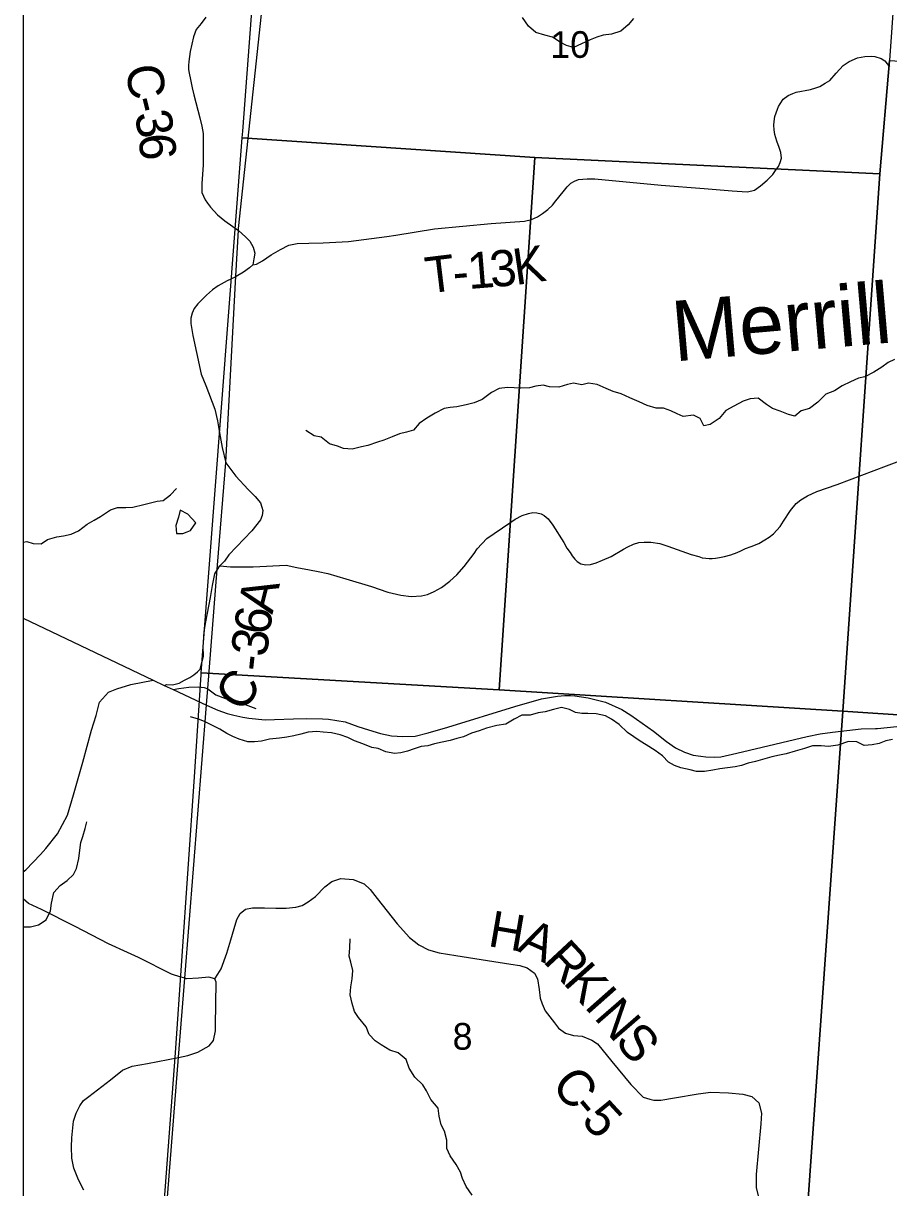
# Model space of a CAD drawing. Extents: x -8.2 to 34, y 0 to 22.
# Drawn here: x 2.1 to 3.458, y 17.043 to 18.871 of the extents above; entities that cross this region are included whole.
import ezdxf

# ---------------------------------------------------------------- set-up
doc = ezdxf.new("R2010")
doc.units = 0
for name, color, linetype in [('GM_X_Corporation', 7, 'Continuous'), ('GM_X_County_Road', 7, 'Continuous'), ('GM_X_County_Road_Text', 7, 'Continuous'), ('GM_X_Minor_Lake', 7, 'Continuous'), ('GM_X_Minor_River', 7, 'Continuous'), ('GM_X_Minor_River_Text', 7, 'Continuous'), ('GM_X_Section_Text', 7, 'Continuous'), ('GM_X_Township_Road', 7, 'Continuous'), ('GM_X_Township_Road_Text', 7, 'Continuous'), ('GM_X_Township_Text', 7, 'Continuous'), ('GM_X_US_Route', 7, 'Continuous'), ('SH_Data', 7, 'Continuous')]:
    doc.layers.add(name, color=color, linetype=linetype)

msp = doc.modelspace()

# ---------------------------------------------------------------- linework, layer by layer
at = {"layer": 'GM_X_Corporation'}
msp.add_lwpolyline([(6.4774, 18.0203), (6.488, 18.1752), (6.5242, 18.7061), (6.5297, 18.7882), (6.5448, 18.981), (6.5455, 18.9878), (6.5461, 19.0017), (6.5463, 19.009), (6.5469, 19.0218), (6.548, 19.0467), (6.5487, 19.0617), (6.5495, 19.0821), (6.5503, 19.0966), (6.5514, 19.1092), (6.5523, 19.118), (6.5529, 19.1264), (6.5537, 19.1382), (6.5541, 19.1447), (6.5536, 19.1514), (6.5814, 19.5334), (6.6608, 20.6695), (6.6768, 20.9), (2.1, 20.9), (2.1, 14.1)], dxfattribs=at)
for points in [[(2.4767, 19.0935), (3.474, 19.0276), (3.459, 18.8121), (3.4438, 18.6343), (2.9025, 18.6602), (2.4436, 18.691), (2.4444, 18.7015), (2.4582, 18.8825)], [(4.465, 18.749), (4.3947, 17.7241), (3.3856, 17.7912), (3.4438, 18.6343), (3.459, 18.8121)], [(2.9025, 18.6602), (2.8467, 17.8246), (2.3793, 17.8512), (2.4436, 18.691)], [(3.4438, 18.6343), (3.3856, 17.7912), (2.8467, 17.8246), (2.9025, 18.6602)], [(2.3791, 17.8483), (2.3793, 17.8512), (2.8467, 17.8246), (3.3856, 17.7912), (3.312, 16.7534), (2.3064, 16.8225), (2.3386, 17.2548), (2.3688, 17.6879)], [(3.3856, 17.7912), (4.3947, 17.7241), (4.3249, 16.693), (3.312, 16.7534)]]:
    msp.add_lwpolyline(points, close=True, dxfattribs=at)
at = {"layer": 'GM_X_County_Road'}
for points in [[(2.3864, 18.8801), (2.3791, 18.8703), (2.3714, 18.861), (2.3673, 18.8497), (2.3644, 18.8381), (2.3616, 18.8265), (2.3606, 18.8187), (2.3595, 18.8107), (2.359, 18.8046), (2.3593, 18.7981), (2.3603, 18.7927), (2.3624, 18.7824), (2.3652, 18.7692), (2.3678, 18.7587), (2.3771, 18.7226), (2.3799, 18.7094), (2.382, 18.6978), (2.3822, 18.6483), (2.3799, 18.6191), (2.3802, 18.605), (2.3853, 18.5939), (2.3892, 18.5885)], [(2.3892, 18.5885), (2.3936, 18.5823), (2.4049, 18.5699), (2.416, 18.5609), (2.4374, 18.5456), (2.4488, 18.5358), (2.4552, 18.5286), (2.4604, 18.5196), (2.4632, 18.5098), (2.4617, 18.5008), (2.4602, 18.4916), (2.4549, 18.4869), (2.4456, 18.4803), (2.4338, 18.4731), (2.4322, 18.4721), (2.4199, 18.4663), (2.406, 18.4585), (2.3971, 18.4522), (2.3874, 18.4441), (2.3804, 18.4374), (2.3738, 18.4302), (2.3683, 18.423), (2.3651, 18.416), (2.363, 18.4077), (2.3626, 18.3998), (2.3658, 18.3808), (2.3715, 18.3542), (2.3793, 18.3201), (2.3862, 18.3025), (2.4005, 18.2649), (2.4045, 18.247), (2.4079, 18.2277), (2.4119, 18.2052), (2.4179, 18.1808), (2.4335, 18.1598), (2.4528, 18.139), (2.4637, 18.1282), (2.472, 18.1181), (2.4742, 18.1111), (2.4759, 18.1058), (2.4748, 18.0984), (2.4723, 18.0914), (2.4587, 18.0744), (2.4227, 18.0363), (2.4159, 18.0264), (2.4084, 18.0194), (2.425, 18.0175), (2.434, 18.0175), (2.4608, 18.0179), (2.5126, 18.0204), (2.5292, 18.0167), (2.5491, 18.013), (2.5626, 18.0105), (2.578, 18.0072), (2.6058, 17.9989), (2.6461, 17.9866), (2.6721, 17.978), (2.6922, 17.9731), (2.7086, 17.971), (2.7247, 17.972), (2.7342, 17.9741), (2.7446, 17.9788), (2.7563, 17.9854), (2.769, 17.9952), (2.78, 18.0052), (2.7915, 18.0181), (2.8072, 18.0384), (2.812, 18.0459), (2.8273, 18.0619), (2.8633, 18.0867), (2.8719, 18.0924), (2.8826, 18.0984), (2.8924, 18.1014), (2.8996, 18.1029), (2.9059, 18.1025), (2.9123, 18.1008), (2.917, 18.0982), (2.9235, 18.0928), (2.9309, 18.0828), (2.9479, 18.0558), (2.953, 18.0472), (2.9579, 18.04), (2.9612, 18.0347), (2.9651, 18.0296), (2.9688, 18.0261), (2.9749, 18.0224), (2.9825, 18.021), (2.9901, 18.0214), (2.9989, 18.024), (3.0085, 18.0279), (3.0222, 18.0339), (3.0417, 18.0455), (3.0484, 18.0488), (3.0572, 18.0533), (3.0656, 18.0556), (3.074, 18.0564), (3.0847, 18.0562), (3.0986, 18.0543), (3.1111, 18.0503), (3.1481, 18.0369), (3.1598, 18.0337), (3.1653, 18.0318), (3.1709, 18.031), (3.1762, 18.0308), (3.1807, 18.0306), (3.1858, 18.0314), (3.1924, 18.0324), (3.2001, 18.0337), (3.2102, 18.0363), (3.2198, 18.04), (3.2257, 18.0425), (3.2333, 18.0462), (3.2421, 18.0498), (3.2538, 18.0543), (3.2636, 18.0599), (3.2704, 18.064), (3.2772, 18.0693), (3.2874, 18.0808), (3.2929, 18.0892), (3.3036, 18.1059), (3.3125, 18.1168), (3.3197, 18.1229), (3.3304, 18.1293), (3.3449, 18.1358), (3.377, 18.1467), (3.4542, 18.1762), (3.471, 18.1827)], [(2.3825, 17.8795), (2.3824, 17.8911), (2.384, 17.9159), (2.3862, 17.9315), (2.3939, 17.9694), (2.3971, 17.9881), (2.4005, 18.0067), (2.4046, 18.0132), (2.4084, 18.0194)], [(2.3211, 17.8313), (2.3251, 17.8328), (2.334, 17.8324), (2.3446, 17.8352), (2.3528, 17.8396), (2.3615, 17.8437), (2.3675, 17.8481), (2.3732, 17.8528), (2.3774, 17.8572), (2.38, 17.8674), (2.3825, 17.8775), (2.3825, 17.8795)], [(2.1, 17.5387), (2.1039, 17.5422), (2.127, 17.5659), (2.1355, 17.5754), (2.1536, 17.5985), (2.1691, 17.628), (2.1789, 17.6596), (2.1932, 17.7112), (2.2071, 17.7612), (2.2141, 17.7843), (2.2198, 17.8051), (2.2339, 17.8211), (2.2467, 17.8264), (2.2688, 17.8331), (2.3036, 17.8397)], [(2.4004, 17.3708), (2.405, 17.3782), (2.4105, 17.3868), (2.4195, 17.4111), (2.4258, 17.4323), (2.4311, 17.4499), (2.4352, 17.4641), (2.4403, 17.4735), (2.4485, 17.4801), (2.4597, 17.4823), (2.4783, 17.4825), (2.4962, 17.4821), (2.5126, 17.4817), (2.5277, 17.4835), (2.5374, 17.4859), (2.5472, 17.4916), (2.5583, 17.5003), (2.5729, 17.5154), (2.584, 17.5237), (2.5981, 17.5286), (2.6175, 17.527), (2.6346, 17.5203), (2.6442, 17.5111), (2.6552, 17.497), (2.6865, 17.4574), (2.7057, 17.4358), (2.7204, 17.4245), (2.7355, 17.4164), (2.7526, 17.4117), (2.7787, 17.4074), (2.8283, 17.4), (2.8649, 17.3939), (2.8792, 17.3917), (2.8908, 17.3882), (2.902, 17.3798), (2.9067, 17.3709), (2.9094, 17.3545), (2.9112, 17.3406), (2.9141, 17.3317), (2.9188, 17.321), (2.9335, 17.3019), (2.9398, 17.2935), (2.9508, 17.2855), (2.9633, 17.2821), (2.9768, 17.281), (2.9921, 17.2749), (3.001, 17.2688), (3.0233, 17.2412), (3.0531, 17.2053), (3.0727, 17.1855), (3.0829, 17.182), (3.0894, 17.1808), (3.1003, 17.1804), (3.1217, 17.1841), (3.1588, 17.1904), (3.1788, 17.1933), (3.2064, 17.1922), (3.2291, 17.19), (3.2429, 17.1865), (3.254, 17.1765), (3.2581, 17.1602), (3.2572, 17.1432), (3.2498, 17.0638), (3.2501, 17.0436), (3.2561, 17.0178)], [(2.2633, 17.4124), (2.2337, 17.426), (2.1812, 17.4531), (2.1284, 17.4799), (2.1082, 17.4895), (2.1, 17.4966)], [(2.4015, 17.2978), (2.4024, 17.3659), (2.4004, 17.3708), (2.3913, 17.3737), (2.3748, 17.3723), (2.3564, 17.3711), (2.3537, 17.3718), (2.3472, 17.3735), (2.3327, 17.3784), (2.2805, 17.4045), (2.2633, 17.4124)], [(2.1951, 17.0395), (2.1864, 17.0556), (2.1795, 17.074), (2.1764, 17.0893), (2.1758, 17.1071), (2.1763, 17.1213), (2.1789, 17.1475), (2.1829, 17.1601), (2.1889, 17.1716), (2.1947, 17.18), (2.2026, 17.1863), (2.2367, 17.2127), (2.2559, 17.2274), (2.2707, 17.234), (2.2947, 17.238), (2.3433, 17.2474), (2.358, 17.2509), (2.3739, 17.2559), (2.3918, 17.2657), (2.3983, 17.2741), (2.4014, 17.2894), (2.4015, 17.2978)]]:
    msp.add_lwpolyline(points, dxfattribs=at)
at = {"layer": 'GM_X_Minor_Lake'}
for points in [[(2.3459, 18.1065), (2.3436, 18.0955), (2.3391, 18.0826), (2.3406, 18.0697), (2.3505, 18.0697), (2.3571, 18.0725)], [(2.3571, 18.0725), (2.3622, 18.0747), (2.3709, 18.0868), (2.3584, 18.1004), (2.3459, 18.1065)]]:
    msp.add_lwpolyline(points, dxfattribs=at)
at = {"layer": 'GM_X_Minor_River'}
for points in [[(3.0576, 18.8782), (3.0489, 18.8683), (3.0375, 18.8584), (3.0228, 18.8539), (3.0099, 18.852), (3.0001, 18.8489), (2.9895, 18.8448), (2.9758, 18.8387), (2.963, 18.833), (2.9524, 18.836), (2.9425, 18.8409), (2.9304, 18.8489), (2.9183, 18.8519), (2.9043, 18.8561), (2.8929, 18.8663), (2.883, 18.8796)], [(3.4668, 18.3432), (3.457, 18.3383), (3.4471, 18.331), (3.4343, 18.3234), (3.4203, 18.3158), (3.4104, 18.3135), (3.3976, 18.3082), (3.3847, 18.3018), (3.3726, 18.2938), (3.3589, 18.2888), (3.3465, 18.2763), (3.3336, 18.266), (3.3203, 18.2626), (3.3105, 18.2539)], [(3.3105, 18.2539), (3.3006, 18.2565), (3.2874, 18.2618), (3.2756, 18.2659), (3.2658, 18.2724), (3.2529, 18.2826), (3.2404, 18.2814), (3.2294, 18.2776), (3.2146, 18.27), (3.2025, 18.2632), (3.1919, 18.2507), (3.1779, 18.2408), (3.1677, 18.2392), (3.162, 18.2502), (3.1514, 18.2555), (3.1355, 18.2536), (3.126, 18.2578), (3.1158, 18.2627), (3.1044, 18.2665), (3.0931, 18.2668), (3.0787, 18.2706), (3.0665, 18.2766), (3.0514, 18.2827), (3.0381, 18.2891), (3.0256, 18.2929), (3.0146, 18.2974), (3.0006, 18.3039), (2.9869, 18.3061), (2.9763, 18.3034), (2.9635, 18.3061), (2.9536, 18.3038), (2.9404, 18.2996), (2.9256, 18.3003), (2.9154, 18.3026), (2.904, 18.3011), (2.8941, 18.2984), (2.8805, 18.298), (2.8703, 18.2987), (2.8597, 18.2991), (2.8468, 18.2976), (2.8347, 18.2915), (2.8199, 18.2801), (2.8074, 18.2748), (2.7949, 18.2721), (2.7802, 18.2687), (2.7699, 18.2679), (2.7601, 18.266), (2.7461, 18.2588), (2.7332, 18.2508), (2.7211, 18.2424), (2.712, 18.2322), (2.7014, 18.2291), (2.6901, 18.2264), (2.6787, 18.2215), (2.6658, 18.2165), (2.6556, 18.2135), (2.6408, 18.2082), (2.6306, 18.2059), (2.6162, 18.2021), (2.6026, 18.2032), (2.5931, 18.207), (2.5802, 18.2107), (2.5673, 18.2213), (2.5563, 18.2232), (2.5435, 18.2315)], [(2.1868, 18.0744), (2.2001, 18.0847), (2.2114, 18.0911), (2.2213, 18.0965), (2.2368, 18.1071), (2.2478, 18.1109), (2.261, 18.1106), (2.2716, 18.1113), (2.2891, 18.1155), (2.2997, 18.1182), (2.3099, 18.1205), (2.3197, 18.122), (2.3311, 18.1304), (2.3405, 18.1406)], [(2.1, 18.0564), (2.1054, 18.0572), (2.1156, 18.0542), (2.1278, 18.0535), (2.138, 18.0607), (2.1524, 18.0649), (2.163, 18.0664), (2.1751, 18.0687), (2.1868, 18.0744)], [(3.4638, 17.7467), (3.4532, 17.7448), (3.443, 17.7402), (3.432, 17.7383), (3.4191, 17.7371), (3.4077, 17.7428), (3.3948, 17.7435), (3.3782, 17.7378), (3.3634, 17.7359), (3.352, 17.7367), (3.338, 17.7366), (3.3259, 17.7325), (3.3108, 17.7283), (3.2968, 17.7244), (3.2862, 17.7218), (3.2744, 17.7195), (3.2596, 17.7153), (3.249, 17.7122), (3.2373, 17.7096), (3.2267, 17.7058), (3.2169, 17.7039), (3.2051, 17.7023), (3.1926, 17.7008), (3.182, 17.6985), (3.1688, 17.6962), (3.1563, 17.6962), (3.1464, 17.6988), (3.1316, 17.7022), (3.1218, 17.706), (3.1123, 17.7109), (3.1028, 17.7208), (3.0914, 17.7295), (3.0774, 17.7382), (3.0679, 17.7438), (3.0581, 17.7506), (3.0478, 17.7578), (3.035, 17.77), (3.0228, 17.7787), (3.0133, 17.7836), (2.9986, 17.787), (2.9857, 17.7877), (2.9762, 17.7877), (2.9664, 17.7892), (2.9569, 17.7937), (2.9444, 17.7968), (2.9319, 17.7937), (2.919, 17.7903), (2.9077, 17.7884), (2.8952, 17.7849), (2.8823, 17.7849), (2.8702, 17.7788), (2.8569, 17.7708), (2.8429, 17.7685), (2.827, 17.7644), (2.8153, 17.7602)], [(2.8153, 17.7602), (2.8031, 17.7564), (2.7907, 17.7506), (2.78, 17.748), (2.7698, 17.7453), (2.7573, 17.7423), (2.7452, 17.7396), (2.7346, 17.7369), (2.7244, 17.7354), (2.7134, 17.732), (2.7028, 17.7282), (2.6922, 17.7259), (2.6823, 17.7247), (2.6687, 17.7273), (2.657, 17.7323), (2.6467, 17.7341), (2.6327, 17.7398), (2.6198, 17.7443), (2.6092, 17.7496), (2.5971, 17.7538), (2.5834, 17.7572), (2.5706, 17.7583), (2.5603, 17.759), (2.5467, 17.7579), (2.5353, 17.7548), (2.5244, 17.7522), (2.5134, 17.7503), (2.502, 17.7487), (2.4865, 17.7472), (2.4736, 17.7441), (2.463, 17.743), (2.4524, 17.743), (2.4388, 17.7471), (2.4289, 17.7513), (2.4194, 17.7558), (2.4084, 17.7626), (2.3842, 17.7747), (2.3747, 17.7785), (2.3622, 17.7823)], [(2.1429, 17.4778), (2.144, 17.49), (2.1478, 17.5063), (2.1576, 17.5173), (2.1689, 17.5253), (2.1788, 17.5348), (2.1833, 17.5443), (2.1871, 17.5598), (2.1886, 17.5731), (2.1901, 17.5848), (2.1935, 17.5943), (2.1973, 17.6072), (2.1995, 17.6175)], [(2.1, 17.4533), (2.1016, 17.4528), (2.1111, 17.4528), (2.124, 17.4558), (2.1361, 17.4634), (2.1429, 17.4778)], [(2.8044, 17.0317), (2.7946, 17.0449), (2.7892, 17.0578), (2.7858, 17.0677), (2.7794, 17.0798), (2.7695, 17.093), (2.7646, 17.1048), (2.7645, 17.1177), (2.7611, 17.1321), (2.7558, 17.1416), (2.7524, 17.1552), (2.7508, 17.1681), (2.7395, 17.1814), (2.7326, 17.195), (2.7269, 17.2045), (2.7144, 17.2166), (2.7053, 17.231), (2.7007, 17.2446), (2.6879, 17.2549), (2.675, 17.259), (2.6617, 17.2673), (2.6522, 17.2738), (2.6424, 17.2836), (2.6378, 17.2957), (2.6257, 17.3101), (2.6196, 17.3196), (2.6158, 17.3321), (2.6131, 17.3458), (2.6139, 17.3587), (2.6161, 17.3712), (2.6172, 17.3841), (2.6138, 17.397), (2.6111, 17.4068), (2.6123, 17.4197), (2.613, 17.4337)]]:
    msp.add_lwpolyline(points, dxfattribs=at)
at = {"layer": 'GM_X_Township_Road'}
for points in [[(2.4602, 18.4916), (2.4657, 18.4926), (2.4752, 18.4977), (2.489, 18.5072), (2.5034, 18.5159), (2.5165, 18.5225), (2.5299, 18.525), (2.5479, 18.5259), (2.5707, 18.5263), (2.6103, 18.528), (2.6704, 18.5362), (2.6845, 18.5384), (2.745, 18.5479), (2.8339, 18.5566), (2.8862, 18.56), (2.8974, 18.5626), (2.9067, 18.5671), (2.9148, 18.5722), (2.923, 18.5786), (2.9305, 18.5851), (2.9357, 18.5923), (2.9471, 18.6062), (2.9531, 18.6139), (2.959, 18.6197), (2.965, 18.6228), (2.9711, 18.6256), (2.9779, 18.6262), (2.9847, 18.6266), (2.9965, 18.6264), (3.1007, 18.6167), (3.1682, 18.6114), (3.2123, 18.6076), (3.2279, 18.6067), (3.2362, 18.6061), (3.247, 18.6086), (3.2567, 18.6157), (3.2671, 18.6243), (3.2758, 18.6332), (3.2802, 18.6396), (3.2847, 18.6459), (3.2876, 18.6523), (3.2898, 18.6593), (3.2885, 18.6677), (3.2857, 18.676), (3.2823, 18.6857), (3.2792, 18.6963), (3.2781, 18.7033), (3.2777, 18.7109), (3.2779, 18.7168), (3.2792, 18.7243), (3.2811, 18.7304), (3.2832, 18.7361), (3.2849, 18.7401), (3.2876, 18.7444), (3.2923, 18.7518), (3.2999, 18.7573), (3.3073, 18.7605), (3.3128, 18.7626), (3.3349, 18.767), (3.3433, 18.7694), (3.3495, 18.7715), (3.3582, 18.7768), (3.3656, 18.7812), (3.3755, 18.7922), (3.3861, 18.8043), (3.3956, 18.8106), (3.4088, 18.8164), (3.4202, 18.8187), (3.4304, 18.8191), (3.4361, 18.8187), (3.4458, 18.8155), (3.4515, 18.8119), (3.4591, 18.8022)], [(2.3351, 17.8251), (2.3442, 17.8265), (2.3595, 17.8288), (2.3745, 17.8295), (2.3836, 17.828), (2.3897, 17.8261)], [(2.3897, 17.8261), (2.4022, 17.817), (2.417, 17.8111), (2.4331, 17.807), (2.4437, 17.8034), (2.4651, 17.7952)]]:
    msp.add_lwpolyline(points, dxfattribs=at)
at = {"layer": 'GM_X_Township_Text'}
msp.add_lwpolyline([(2.227, 15.7788), (2.2908, 16.5825), (2.3045, 16.7554), (2.3047, 16.7573), (2.3109, 16.8355), (2.3177, 16.9219), (2.3436, 17.248), (2.3535, 17.3723), (2.3875, 17.8009), (2.3895, 17.8266), (2.4044, 18.0138), (2.4049, 18.02), (2.4177, 18.1814), (2.4336, 18.4736), (2.4376, 18.5459), (2.4377, 18.5489), (2.4735, 18.885), (2.5013, 19.2713), (2.5435, 19.8534), (2.5683, 20.2001), (2.5873, 20.4639), (2.6187, 20.9)], dxfattribs=at)
at = {"layer": 'GM_X_US_Route'}
for points in [[(2.1, 17.9369), (2.1558, 17.9103), (2.3036, 17.8397), (2.3211, 17.8313), (2.3351, 17.8251)], [(2.3351, 17.8251), (2.3873, 17.8006), (2.405, 17.7928), (2.4199, 17.7874), (2.4301, 17.7846), (2.4444, 17.7818), (2.4537, 17.78), (2.4796, 17.7777), (2.4939, 17.7779), (2.5237, 17.779), (2.5436, 17.7794), (2.5693, 17.779), (2.5791, 17.7783), (2.592, 17.7764), (2.6052, 17.7742), (2.6251, 17.7671), (2.6418, 17.7619), (2.6606, 17.7558), (2.6775, 17.7526), (2.6956, 17.7515), (2.7146, 17.7521), (2.7352, 17.7571), (2.7659, 17.7658), (2.871, 17.7982), (2.9131, 17.8107), (2.9382, 17.8146), (2.9497, 17.8155), (2.9587, 17.8155), (2.9655, 17.8153), (2.9864, 17.8118), (3.0135, 17.8051), (3.0392, 17.7939), (3.0532, 17.785), (3.0887, 17.7595), (3.1092, 17.7433), (3.1231, 17.7338), (3.1376, 17.7268), (3.1508, 17.7223), (3.1631, 17.7204), (3.1709, 17.7193), (3.1843, 17.7191), (3.1944, 17.7195), (3.2193, 17.7251), (3.2394, 17.7301), (3.33, 17.7513), (3.3505, 17.7556), (3.3696, 17.7584), (3.4145, 17.7632), (3.4372, 17.7638), (3.4402, 17.7641)], [(3.4402, 17.7641), (3.4703, 17.7671)]]:
    msp.add_lwpolyline(points, dxfattribs=at)
at = {"layer": 'SH_Data'}
msp.add_line((2.1, 20.9), (2.1, 14.1), dxfattribs=at)

# ---------------------------------------------------------------- texts
at = {"layer": 'GM_X_County_Road_Text'}
for s, rotation, p in [('C', 278.2399, (2.2604, 18.8026)), ('-', 283.8873, (2.2683, 18.7504)), ('3', 282.3346, (2.2738, 18.7281)), ('6', 274.2606, (2.281, 18.696)), ('A', 76.0866, (2.4907, 17.9421)), ('6', 82.2299, (2.4863, 17.9093)), ('3', 82.1199, (2.4815, 17.8748)), ('-', 83.7695, (2.479, 17.8522)), ('C', 58.9748, (2.4466, 17.7873)), ('H', 350.3005, (2.8275, 17.4227)), ('A', 336.1174, (2.8732, 17.4153)), ('R', 312.9269, (2.914, 17.3986)), ('K', 311.6057, (2.9456, 17.3647)), ('I', 311.5259, (2.9788, 17.3273)), ('N', 310.9656, (2.9941, 17.3099)), ('S', 309.7685, (3.0267, 17.2724)), ('C', 309.5022, (2.9269, 17.2037)), ('-', 310.2392, (2.9571, 17.1671)), ('5', 312.5997, (2.9739, 17.1474))]:
    msp.add_text(s, height=0.0568, rotation=rotation, dxfattribs=at).set_placement(p)
at = {"layer": 'GM_X_Minor_River_Text'}
msp.add_text('Merrill', height=0.0947, rotation=5.0034, dxfattribs=at).set_placement((3.1217, 18.3399))
at = {"layer": 'GM_X_Section_Text'}
for s, height, p in [('10', 0.04186, (2.9269, 18.8165)), ('8', 0.0419, (2.7736, 17.2598))]:
    msp.add_text(s, height=height, rotation=0, dxfattribs=at).set_placement(p)
at = {"layer": 'GM_X_Township_Road_Text'}
for s, rotation, p in [('3', 4.7312, (2.8339, 18.4564)), ('K', 8.2473, (2.8726, 18.4597)), ('T', 6.9602, (2.7341, 18.4465)), ('1', 4.6625, (2.799, 18.4536)), ('-', 4.9322, (2.7758, 18.4516))]:
    msp.add_text(s, height=0.0568, rotation=rotation, dxfattribs=at).set_placement(p)

doc.saveas('drawing.dxf')
